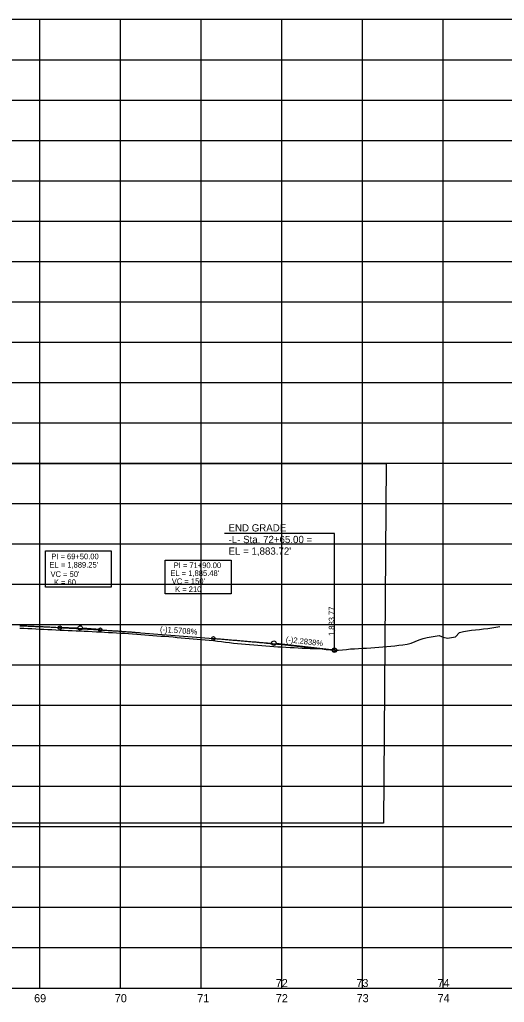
# Model space of a CAD drawing. Extents: x 553912 to 567693, y 512355 to 537539.
# Drawn here: x 563124 to 563725, y 513588 to 514805 of the extents above; entities that cross this region are included whole.
import ezdxf

# ---------------------------------------------------------------- set-up
doc = ezdxf.new("R2010")
doc.units = 0
for name, color, linetype in [('Exist Profile Cell', 7, 'Continuous'), ('Exist Vertical Profile Ground Line', 7, 'Continuous'), ('Exist Vertical Profile Horizontal Axis Label Major', 7, 'Continuous'), ('Prop Vertical Profile Curve Label', 7, 'Continuous'), ('Prop Vertical Profile Grade', 7, 'Continuous'), ('Prop Vertical Profile Grade Label', 7, 'Continuous'), ('Prop VPI Label', 7, 'Continuous'), ('Scratch_Level_5', 7, 'Continuous'), ('Sheet Profile Grid Major CELL', 7, 'Continuous')]:
    doc.layers.add(name, color=color, linetype=linetype)

msp = doc.modelspace()

# ---------------------------------------------------------------- linework, layer by layer
at = {"layer": 'Exist Profile Cell'}
msp.add_line((557249.5, 513605.4), (563849.5, 513605.4), dxfattribs=at)
msp.add_line((557249.5, 513605.4), (563849.5, 513605.4), dxfattribs=at)
at = {"layer": 'Exist Vertical Profile Ground Line'}
for points in [[(563249.5, 514045.3), (563254.5, 514045), (563259.5, 514044.6), (563264.5, 514044.3), (563269.5, 514043.9), (563274.5, 514043.5), (563279.5, 514043.2), (563284.5, 514042.8), (563289.5, 514042.4), (563294.5, 514042), (563299.5, 514041.6), (563304.5, 514041.3), (563309.5, 514040.9), (563314.5, 514040.5), (563319.5, 514040), (563324.5, 514039.6), (563329.5, 514039.2), (563334.5, 514038.8), (563339.5, 514038.3), (563344.5, 514037.9), (563349.5, 514037.5), (563354.5, 514037.1), (563359.5, 514036.6), (563364.5, 514036), (563369.5, 514035.3), (563374.5, 514034.7), (563379.5, 514034.1), (563384.5, 514033.5), (563389.5, 514033), (563394.5, 514032.5), (563399.5, 514032), (563404.5, 514031.6), (563409.5, 514031.1), (563414.5, 514030.6), (563419.5, 514030.2), (563424.5, 514029.8), (563429.5, 514029.4), (563434.5, 514029.1), (563439.5, 514028.7), (563444.5, 514028.4), (563449.5, 514028.1), (563454.5, 514027.7), (563459.5, 514027.5), (563464.5, 514027.3), (563469.5, 514027), (563474.5, 514026.8), (563479.5, 514026.6), (563484.5, 514026.4), (563489.5, 514026.2), (563494.5, 514026), (563499.5, 514025.7), (563504.5, 514025.1), (563509.5, 514024.6), (563514.5, 514024), (563519.5, 514024.2), (563524.5, 514024.7), (563529.5, 514025.1), (563534.5, 514025.6), (563539.5, 514025.9), (563544.5, 514026.2), (563549.5, 514026.5), (563554.5, 514026.8), (563559.5, 514027.2), (563564.5, 514027.4), (563569.5, 514027.7), (563574.5, 514028.1), (563579.5, 514028.6), (563584.5, 514029.1), (563589.5, 514029.7), (563594.5, 514030.2), (563599.5, 514030.8), (563604.5, 514031.7), (563609.5, 514032.7), (563614.5, 514034.8), (563619.5, 514036.8), (563624.5, 514038.8), (563629.5, 514040), (563634.5, 514040.8), (563639.5, 514041.6), (563644.5, 514042.3), (563649.5, 514040.3), (563654.5, 514039), (563659.5, 514039.7), (563664.5, 514040.6), (563669.5, 514046.2), (563674.5, 514047.1), (563679.5, 514047.9), (563684.5, 514048.8), (563689.5, 514049.3), (563694.5, 514049.8), (563699.5, 514050.4), (563704.5, 514051.1), (563709.5, 514051.9), (563714.5, 514052.6), (563719.5, 514053.4), (563719.6, 514053.4)], [(563249.5, 514045.3), (563254.5, 514045), (563259.5, 514044.6), (563264.5, 514044.3), (563269.5, 514043.9), (563274.5, 514043.5), (563279.5, 514043.2), (563284.5, 514042.8), (563289.5, 514042.4), (563294.5, 514042), (563299.5, 514041.6), (563304.5, 514041.3), (563309.5, 514040.9), (563314.5, 514040.5), (563319.5, 514040), (563324.5, 514039.6), (563329.5, 514039.2), (563334.5, 514038.8), (563339.5, 514038.3), (563344.5, 514037.9), (563349.5, 514037.5), (563354.5, 514037.1), (563359.5, 514036.6), (563364.5, 514036), (563369.5, 514035.3), (563374.5, 514034.7), (563379.5, 514034.1), (563384.5, 514033.5), (563389.5, 514033), (563394.5, 514032.5), (563399.5, 514032), (563404.5, 514031.6), (563409.5, 514031.1), (563414.5, 514030.6), (563419.5, 514030.2), (563424.5, 514029.8), (563429.5, 514029.4), (563434.5, 514029.1), (563439.5, 514028.7), (563444.5, 514028.4), (563449.5, 514028.1), (563454.5, 514027.7), (563459.5, 514027.5), (563464.5, 514027.3), (563469.5, 514027), (563474.5, 514026.8), (563479.5, 514026.6), (563484.5, 514026.4), (563489.5, 514026.2), (563494.5, 514026), (563499.5, 514025.7), (563504.5, 514025.1), (563509.5, 514024.6), (563514.5, 514024), (563519.5, 514024.2), (563524.5, 514024.7), (563529.5, 514025.1), (563534.5, 514025.6), (563539.5, 514025.9), (563544.5, 514026.2), (563549.5, 514026.5), (563554.5, 514026.8), (563559.5, 514027.2), (563564.5, 514027.4), (563569.5, 514027.7), (563574.5, 514028.1), (563579.5, 514028.6), (563584.5, 514029.1), (563589.5, 514029.7), (563594.5, 514030.2), (563599.5, 514030.8), (563604.5, 514031.7), (563609.5, 514032.7), (563614.5, 514034.8), (563619.5, 514036.8), (563624.5, 514038.8), (563629.5, 514040), (563634.5, 514040.8), (563639.5, 514041.6), (563644.5, 514042.3), (563649.5, 514040.3), (563654.5, 514039), (563659.5, 514039.7), (563664.5, 514040.6), (563669.5, 514046.2), (563674.5, 514047.1), (563679.5, 514047.9), (563684.5, 514048.8), (563689.5, 514049.3), (563694.5, 514049.8), (563699.5, 514050.4), (563704.5, 514051.1), (563709.5, 514051.9), (563714.5, 514052.6), (563719.5, 514053.4), (563719.6, 514053.4)], [(563124.5, 514051.6), (563129.5, 514051.3), (563134.5, 514051.1), (563139.5, 514050.8), (563144.5, 514050.6), (563149.5, 514050.3), (563154.5, 514050.1), (563159.5, 514049.8), (563164.5, 514049.6), (563169.5, 514049.4), (563174.5, 514049.1), (563179.5, 514048.9), (563184.5, 514048.7), (563189.5, 514048.4), (563194.5, 514048.2), (563199.5, 514048), (563204.5, 514047.8), (563209.5, 514047.5), (563214.5, 514047.3), (563219.5, 514047), (563224.5, 514046.7), (563229.5, 514046.5), (563234.5, 514046.2), (563239.5, 514045.9), (563244.5, 514045.6), (563249.5, 514045.3)], [(563124.5, 514051.6), (563129.5, 514051.3), (563134.5, 514051.1), (563139.5, 514050.8), (563144.5, 514050.6), (563149.5, 514050.3), (563154.5, 514050.1), (563159.5, 514049.8), (563164.5, 514049.6), (563169.5, 514049.4), (563174.5, 514049.1), (563179.5, 514048.9), (563184.5, 514048.7), (563189.5, 514048.4), (563194.5, 514048.2), (563199.5, 514048), (563204.5, 514047.8), (563209.5, 514047.5), (563214.5, 514047.3), (563219.5, 514047), (563224.5, 514046.7), (563229.5, 514046.5), (563234.5, 514046.2), (563239.5, 514045.9), (563244.5, 514045.6), (563249.5, 514045.3)]]:
    msp.add_lwpolyline(points, dxfattribs=at)
at = {"layer": 'Prop Vertical Profile Curve Label'}
for centre in [(563174.3, 514052), (563224.5, 514049.5), (563364.5, 514038.7), (563514.5, 514024.2)]:
    msp.add_circle(centre, 2.25, dxfattribs=at)
at = {"layer": 'Prop Vertical Profile Grade'}
msp.add_line((563274.5, 514045.8), (563364.5, 514038.7), dxfattribs=at)
for points in [[(563124.5, 514054.4), (563127.5, 514054.3), (563130.5, 514054.2), (563133.5, 514054.1), (563136.5, 514053.9), (563139.5, 514053.8), (563142.5, 514053.7), (563145.5, 514053.6), (563148.5, 514053.4), (563151.5, 514053.3), (563154.5, 514053.2), (563157.5, 514053), (563160.5, 514052.9), (563163.5, 514052.8), (563166.5, 514052.6), (563169.5, 514052.5), (563172.5, 514052.3), (563175.5, 514052.2), (563178.5, 514052), (563181.5, 514051.9), (563184.5, 514051.7), (563187.5, 514051.5), (563190.5, 514051.4), (563193.5, 514051.2), (563196.5, 514051), (563199.5, 514050.9), (563202.5, 514050.7), (563205.5, 514050.5), (563208.5, 514050.3), (563211.5, 514050.2), (563214.5, 514050), (563217.5, 514049.8), (563220.5, 514049.6), (563223.5, 514049.4), (563226.5, 514049.2), (563229.5, 514049), (563232.5, 514048.8), (563235.5, 514048.6), (563238.5, 514048.4), (563241.5, 514048.2), (563244.5, 514048), (563247.5, 514047.8), (563250.5, 514047.6), (563253.5, 514047.3), (563256.5, 514047.1), (563259.5, 514046.9), (563262.5, 514046.7), (563265.5, 514046.5), (563268.5, 514046.2), (563271.5, 514046), (563274.5, 514045.8)], [(563364.5, 514038.7), (563367.5, 514038.5), (563370.5, 514038.2), (563373.5, 514038), (563376.5, 514037.7), (563379.5, 514037.5), (563382.5, 514037.2), (563385.5, 514037), (563388.5, 514036.7), (563391.5, 514036.5), (563394.5, 514036.2), (563397.5, 514036), (563400.5, 514035.7), (563403.5, 514035.4), (563406.5, 514035.2), (563409.5, 514034.9), (563412.5, 514034.6), (563415.5, 514034.4), (563418.5, 514034.1), (563421.5, 514033.8), (563424.5, 514033.6), (563427.5, 514033.3), (563430.5, 514033), (563433.5, 514032.7), (563436.5, 514032.4), (563439.5, 514032.1), (563442.5, 514031.8), (563445.5, 514031.5), (563448.5, 514031.3), (563451.5, 514031), (563454.5, 514030.7), (563457.5, 514030.4), (563460.5, 514030.1), (563463.5, 514029.8), (563466.5, 514029.4), (563469.5, 514029.1), (563472.5, 514028.8), (563475.5, 514028.5), (563478.5, 514028.2), (563481.5, 514027.9), (563484.5, 514027.6), (563487.5, 514027.2), (563490.5, 514026.9), (563493.5, 514026.6), (563496.5, 514026.3), (563499.5, 514025.9), (563502.5, 514025.6), (563505.5, 514025.3), (563508.5, 514024.9), (563511.5, 514024.6), (563514.5, 514024.2)]]:
    msp.add_spline(points, degree=3, dxfattribs=at)
at = {"layer": 'Prop VPI Label'}
for p, q in [((563514.5, 514168.6), (563378.4, 514168.6)), ((563514.5, 514024), (563514.5, 514168.6)), ((563174, 514052.6), (563196.7, 514051.8)), ((563224.2, 514049.7), (563202.2, 514051.4)), ((563364.5, 514038.7), (563436.7, 514033)), ((563514.5, 514024.2), (563442.2, 514032.5))]:
    msp.add_line(p, q, dxfattribs=at)
for points in [[(563156.6, 514147.4), (563238, 514147.4), (563238, 514102), (563156.6, 514102)], [(563304.8, 514135.8), (563386.7, 514135.8), (563386.7, 514093.8), (563304.8, 514093.8)]]:
    msp.add_lwpolyline(points, close=True, dxfattribs=at)
for centre in [(563199.5, 514051.7), (563439.5, 514032.8), (563514.5, 514024.2)]:
    msp.add_circle(centre, 2.75, dxfattribs=at)
at = {"layer": 'Scratch_Level_5'}
msp.add_lwpolyline([(562849.5, 514255.4), (563578.6, 514255.4), (563575.5, 513809.8), (562846.4, 513809.8)], close=True, dxfattribs=at)
at = {"layer": 'Sheet Profile Grid Major CELL'}
for p, q in [((563849.5, 514805.4), (557249.5, 514805.4)), ((563149.5, 513605.4), (563149.5, 514805.4)), ((563249.5, 513605.4), (563249.5, 514805.4)), ((563349.5, 513605.4), (563349.5, 514805.4)), ((563449.5, 513605.4), (563449.5, 514805.4)), ((563549.5, 513605.4), (563549.5, 514805.4)), ((563649.5, 513605.4), (563649.5, 514805.4)), ((563849.5, 514755.4), (557249.5, 514755.4)), ((563849.5, 514705.4), (557249.5, 514705.4)), ((563849.5, 514655.4), (557249.5, 514655.4)), ((563849.5, 514605.4), (557249.5, 514605.4)), ((563849.5, 514555.4), (557249.5, 514555.4)), ((563849.5, 514505.4), (557249.5, 514505.4)), ((563849.5, 514455.4), (557249.5, 514455.4)), ((563849.5, 514405.4), (557249.5, 514405.4)), ((563849.5, 514355.4), (557249.5, 514355.4)), ((563849.5, 514305.4), (557249.5, 514305.4)), ((563849.5, 514255.4), (557249.5, 514255.4)), ((563849.5, 514205.4), (557249.5, 514205.4)), ((563849.5, 514155.4), (557249.5, 514155.4)), ((563849.5, 514105.4), (557249.5, 514105.4)), ((563849.5, 514055.4), (557249.5, 514055.4)), ((563849.5, 514005.4), (557249.5, 514005.4)), ((563849.5, 513955.4), (557249.5, 513955.4)), ((563849.5, 513905.4), (557249.5, 513905.4)), ((563849.5, 513855.4), (557249.5, 513855.4)), ((563849.5, 513805.4), (557249.5, 513805.4)), ((563849.5, 513755.4), (557249.5, 513755.4)), ((563849.5, 513705.4), (557249.5, 513705.4)), ((563849.5, 513655.4), (557249.5, 513655.4))]:
    msp.add_line(p, q, dxfattribs=at)

# ---------------------------------------------------------------- texts
at = {"layer": 'Exist Vertical Profile Horizontal Axis Label Major'}
for s, p in [('72', (563441.9, 513606.7)), ('73', (563541.8, 513606.7)), ('74', (563642.3, 513606.7)), ('69', (563142.4, 513587.9)), ('69', (563142.4, 513587.9)), ('70', (563242.4, 513587.9)), ('70', (563242.4, 513587.9)), ('71', (563344.5, 513587.9)), ('71', (563344.5, 513587.9)), ('72', (563442, 513587.9)), ('72', (563442, 513587.9)), ('73', (563542.1, 513587.9)), ('73', (563542.1, 513587.9)), ('74', (563642.4, 513587.9)), ('74', (563642.4, 513587.9))]:
    msp.add_text(s, height=10, dxfattribs=at).set_placement(p)
at = {"layer": 'Prop Vertical Profile Curve Label'}
for s, p in [("VC = 50'", (563162.7, 514114.9)), ("VC = 150'", (563313, 514106.1)), ('K = 60', (563166.9, 514104.8)), ('K = 210', (563317.1, 514096.1))]:
    msp.add_text(s, height=7, dxfattribs=at).set_placement(p)
at = {"layer": 'Prop Vertical Profile Grade Label'}
for s, rotation, p in [('(-)1.5708%', 355.5091, (563298.2, 514046.9)), ('(-)2.2838%', 353.4855, (563454, 514034.2))]:
    msp.add_text(s, height=7, rotation=rotation, dxfattribs=at).set_placement(p)
at = {"layer": 'Prop VPI Label'}
for s, height, p in [('END GRADE ', 9, (563383.3, 514171.2)), ('-L- Sta. 72+65.00 =', 9, (563383.3, 514156.8)), ("EL = 1,883.72'", 9, (563383.3, 514142.4)), ('PI = 69+50.00', 7, (563163.6, 514136.8)), ("EL = 1,889.25'", 7, (563161.4, 514126.4)), ('PI = 71+90.00', 7, (563315.3, 514125.8)), ("EL = 1,885.48'", 7, (563311.3, 514116))]:
    msp.add_text(s, height=height, dxfattribs=at).set_placement(p)
msp.add_text('1,883.77', height=7, rotation=90, dxfattribs=at).set_placement((563514.5, 514041.7))

doc.saveas('drawing.dxf')
